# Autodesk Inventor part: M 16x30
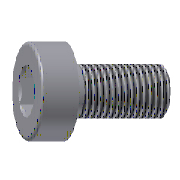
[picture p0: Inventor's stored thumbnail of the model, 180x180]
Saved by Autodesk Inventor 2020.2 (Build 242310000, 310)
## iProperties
Manager: www.cadconsulting.pl
Company: Fabian Stasiak CAD Consulting
Created: 2014-02
Part Number: M 16x30
Material: Stal, miękka
Description: Socket Head Cap Screw DIN 912 - 12.9
Document SubType Name: Modeling
Designer: F.Stasiak
Standard Revision: 1
Manufacturer: DME
Language: pl-PL
Size Designation: 16x30
Categories: <MemberInstance><Categories><Category DisplayName="Forma wtryskowa" InternalName="349578f2-f4d4-4954-8c09-8e99297a61c0" Mnemonic="MOLD"><Category DisplayName="C
Mass: 0.133121 g
Surface Area: 2.01441 cm^2
Volume: 0.133121 cm^3
Density: 7.85 g/cm^3
Appearance: Częściowo polerowana
Catalog Web Link: www.expertbooks.pl
IsCustomPart: 0
Author: F.Stasiak
Subject: Zbiór ćwiczeń. Autodesk Inventor 2020. Kurs Professional
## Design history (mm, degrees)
sketch "Sketch1"
  geometry: L1 (0, -39.2)-(0, 25.2) reference; L2 (8.083, 16)-(12, 16); L3 (12, 16)-(12, 0); L4 (12, 0)-(8, 0); L5 (8, 0)-(8, -30); L6 (8, -30)-(0, -30); L7 (0, 3.794)-(0, -30); L8 (0, 3.794)-(7, 8); L9 (7, 8)-(7, 14.917); L10 (7, 14.917)-(8.083, 16); 1 further point
  constraints: 18 end point, 4 vertical, 3 horizontal, 2 point on line
  dimensions: "d0" = 24 diameter of L3 L1 (= dk); "d1" = 16 distance between parallel lines of L4 L2 (= k); "d2" = 16 diameter of L5 L1 (= d); "d3" = 30 distance between parallel lines of L6 L4 (= L); "d4" = 59 deg angle of L1 L8; "d5" = 45 deg angle of L1 L10; "d6" = 14 diameter of L9 L1 (= sw); "d7" = 16.16581 diameter of L2.start L1 (= 1.1547 x sw); "d8" = 8 distance from line of L8.end L2 (= t)
revolve "Revolution1" sketch "Sketch1" stored, may be unused: angle "d44" = 90 deg
sketch "Sketch2"
  geometry: L1 (0, 8.083)-(7, 4.041); L2 (7, 4.041)-(7, -4.041); L3 (7, -4.041)-(0, -8.083); L4 (0, -8.083)-(-7, -4.041); L5 (-7, -4.041)-(-7, 4.041); L6 (-7, 4.041)-(0, 8.083); 3 further points
  constraints: 12 end point, 2 vertical alignment, 1 coincident, 14 other
extrude "Extrusion1" cut sketch "Sketch2" taper "d9" = 0 deg; stored distance "d45" = 10
thread "Thread1" dims "d10" = 30 (= b), "d11" = 0
chamfer "Chamfer1" distance "d12" = 1 (= 0.5 x P); stored, may be unused: second distance "d50" = 2, angle "d51" = 45 deg
fillet "Fillet1" dims "d13" = 1 (= 0.5 x P)
body "Solid1"
other parameters: "d" = 16 [user parameter; used in 1 equation term], "L" = 30 [user parameter; used in 1 equation term], "dk" = 24 [user parameter; used in 1 equation term], "b" = 30 [user parameter; used in 1 equation term], "k" = 16 [user parameter; used in 1 equation term], "sw" = 14 [user parameter; used in 2 equation terms], "t" = 8 [user parameter; used in 1 equation term], "P" = 2 [user parameter; used in 2 equation terms], "d14" = 0, "d15" = 0, "d55" = 0
